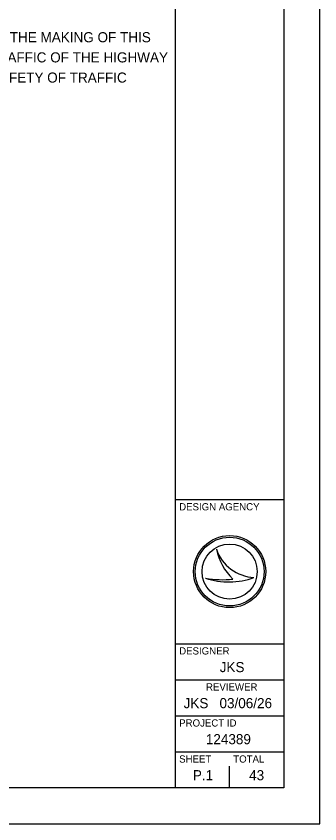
# Model space of a CAD drawing. Extents: x 0 to 34, y 0 to 22.
# Drawn here: x 29.79 to 34, y 0 to 11.21 of the extents above; entities that cross this region are included whole.
import ezdxf

# ---------------------------------------------------------------- set-up
doc = ezdxf.new("R2010")
doc.units = 0
for name, color, linetype in [('SH_Border', 7, 'Continuous'), ('SH_Cut_Line', 7, 'Continuous'), ('SH_Data', 7, 'Continuous')]:
    doc.layers.add(name, color=color, linetype=linetype)

msp = doc.modelspace()

# ---------------------------------------------------------------- linework, layer by layer
at = {"layer": 'SH_Border'}
for p, q in [((32, 0.5), (32, 21.5)), ((32, 4.5), (33.5, 4.5)), ((32, 2.5), (33.5, 2.5)), ((32, 2), (33.5, 2)), ((32, 1.5), (33.5, 1.5)), ((32, 1), (33.5, 1))]:
    msp.add_line(p, q, dxfattribs=at)
msp.add_lwpolyline([(1.5, 21.5), (33.5, 21.5), (33.5, 0.5), (1.5, 0.5)], close=True, dxfattribs=at)
at = {"layer": 'SH_Cut_Line'}
msp.add_lwpolyline([(0, 0), (34, 0), (34, 22), (0, 22)], close=True, dxfattribs=at)
at = {"layer": 'SH_Data'}
for p, q in [((32.567, 3.81), (32.567, 3.81)), ((32.75, 3.5), (32.75, 3.5)), ((32.417, 3.41), (32.417, 3.41)), ((33.087, 3.419), (33.087, 3.419)), ((32.75, 0.5), (32.75, 0.8)), ((32.375, 0.675), (32.375, 0.675))]:
    msp.add_line(p, q, dxfattribs=at)
for radius in [0.5, 0.477, 0.477, 0.382]:
    msp.add_circle((32.75, 3.5), radius, dxfattribs=at)
for centre, radius, start, end in [((33.116, 3.998), 0.58, 198.9257, 198.9319), ((33.347, 3.97), 0.796, 191.6379, 191.6421), ((33.116, 3.998), 0.58, 198.9319, 267.1657), ((33.347, 3.97), 0.796, 191.6421, 226.0947), ((32.739, 4.37), 1.013, 251.4576, 290.0832), ((32.648, 4.654), 1.266, 259.4964, 259.4995), ((32.739, 4.37), 1.013, 251.4527, 251.4576), ((32.648, 4.654), 1.266, 259.4995, 276.6672)]:
    msp.add_arc(centre, radius, start, end, dxfattribs=at)

# ---------------------------------------------------------------- texts
for s, height, p in [(' I HEREBY APPROVE THESE PLANS AND DECLARE THAT THE MAKING OF THIS', 0.14, (24.5, 10.846)), ('IMPROVEMENT WILL NOT REQUIRE THE CLOSING TO TRAFFIC OF THE HIGHWAY', 0.14, (24.5, 10.566)), ('AND THAT PROVISIONS FOR THE MAINTENANCE AND SAFETY OF TRAFFIC', 0.14, (24.5, 10.286)), ('DESIGN AGENCY', 0.1, (32.05, 4.35)), ('DESIGNER', 0.1, (32.05, 2.35)), ('JKS', 0.14, (32.612, 2.105)), ('REVIEWER', 0.1, (32.422, 1.85)), ('JKS', 0.14, (32.112, 1.605)), ('03/06/26', 0.14, (32.609, 1.605)), ('PROJECT ID', 0.1, (32.05, 1.35)), ('124389', 0.14, (32.42, 1.105)), ('SHEET', 0.1, (32.05, 0.85)), ('TOTAL', 0.1, (32.8, 0.85)), ('P.1', 0.14, (32.24, 0.605)), ('43', 0.14, (33.02, 0.605))]:
    msp.add_text(s, height=height, dxfattribs=at).set_placement(p)

doc.saveas('drawing.dxf')
